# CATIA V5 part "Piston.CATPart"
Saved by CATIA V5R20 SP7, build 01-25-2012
Part number: Piston
Bounding box of the stored display mesh (mm): x -20 to 20, y -20 to 20, z 0.581 to 61.5
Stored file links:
  F:\Travaux\Modélisations\CFAO_2011\MMS\MMS_GR1\AA_OK\bmadec\Catia\Piston.CATPart
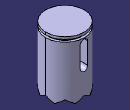
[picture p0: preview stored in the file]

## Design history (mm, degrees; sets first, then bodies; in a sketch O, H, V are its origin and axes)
Body1 (main body)
  Sketch1 on xy-plane, origin (0, 0, 0), H (1, 0, 0), V (0, 1, 0)
    circle A1 centre (0, 0) radius 20
    radius A1 = 20
  Pad1: profile Sketch1, direction (0, 0, 1), length 61.5
  Sketch2 on yz-plane, origin (0, 0, 0), H (0, 1, 0), V (0, 0, 1)
    line L1 (20.9423, 59) -> (17.5, 59)
    line L2 (17.5, 59) -> (17.5, 56.5)
    line L3 (17.5, 56.5) -> (20.9423, 56.5)
    line L4 (20.9423, 56.5) -> (20.9423, 59)
    reference projected line E1 (-20, 61.5) -> (20, 61.5) from edge [face of Pad1 from Sketch1.A1 | end face of Pad1]
    reference projected line E2 through (0, 0) direction (0, 1) from axis of face of Pad1 from Sketch1.A1
    distance L1 E1 = 2.5
    length L2 = 2.5
    distance L2 E2 = 17.5
    horizontal: L1 H, L3 H
    vertical: L2 V, L4 V
  Groove1: profile Sketch2, axis axis of face of Pad1 from Sketch1.A1, angle 360
  Sketch3 on zx-plane, origin (0, 0, 0), H (-1, 0, 0), V (0, 0, 1)
    line L1 (-3.75, 51.85) -> (-3.75, 29.95)
    arc A1 centre (0, 29.95) radius 3.75 from (-3.75, 29.95) to (3.75, 29.95) ccw
    line L2 (3.75, 29.95) -> (3.75, 51.85)
    arc A2 centre (0, 51.85) radius 3.75 from (3.75, 51.85) to (-3.75, 51.85) ccw
    point P6 (0, 51.85)
    reference projected line E1 (-20, 61.5) -> (20, 61.5) from edge [face of Pad1 from Sketch1.A1 | end face of Pad1]
    distance L2 L1 = 7.5
    length L2 = 21.9
    distance P6 E1 = 9.65
    vertical: L1 V
    tangency: A1 L1, L2 A1, A2 L1, A2 L2
    coincidence: P6 V
  Pocket1: profile Sketch3, direction (0, -1, 0), up to face of Pad1 from Sketch1.A1, opposite side up to face of Pad1 from Sketch1.A1
  Sketch4 on start face of Pad1, origin (0, 0, 0), H (1, 0, 0), V (0, -1, 0)
    point P1 (0, 0)
    coincidence: P1 O
  Hole1: placed by Sketch4, at (0, 0, 0) direction (0, 0, 1), diameter 21, depth 58
  Sketch5 on yz-plane, origin (0, 0, 0), H (0, 1, 0), V (0, 0, 1)
    point P1 (-8.6603, 0)
    line L1 (-8.6603, 0) -> (0, 5)
    point P2 (0, 5)
    line L2 (0, 5) -> (8.6603, 0)
    point P3 (8.6603, 0)
    line L3 (8.6603, 0) -> (-8.6603, 0)
    angle L2 L3 = 30
    length L2 V = 5
    coincidence: P1 H, P2 V, P3 H
    horizontal: L3 H
    symmetry: P1 P3 V
  Pocket2: profile Sketch5, direction (-1, 0, 0), up to face of Pad1 from Sketch1.A1, opposite side up to face of Pad1 from Sketch1.A1
  CircPattern1: of Pocket2, instances 4, angular step 45, axis from face of Pad1 from Sketch1.A1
